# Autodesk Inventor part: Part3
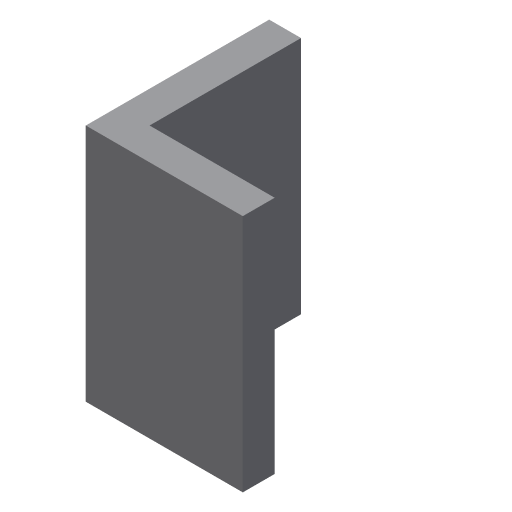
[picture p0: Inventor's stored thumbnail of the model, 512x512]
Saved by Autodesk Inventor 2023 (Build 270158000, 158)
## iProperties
Created: 2009-05
Part Number: Part3
Document SubType Name: Modeling
Designer: Sham
Density: 1 g/cm^3
Material: Generic
Appearance: Default
Author: Sham
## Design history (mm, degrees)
sketch "Sketch1"
  geometry: L1 (-20, 23)-(-20, 0); L2 (-20, 0)-(-0.309, 0); L3 (-0.309, 0)-(-0.309, 4); L4 (-0.309, 4)-(-16, 4); L5 (-16, 4)-(-16, 23); L6 (-16, 23)-(-20, 23)
  constraints: 12 end point, 5 perpendicular
extrude "Extrusion1" new body sketch "Sketch1" distance "d0" = 30; taper "d1" = 0 deg
body "Solid1"
